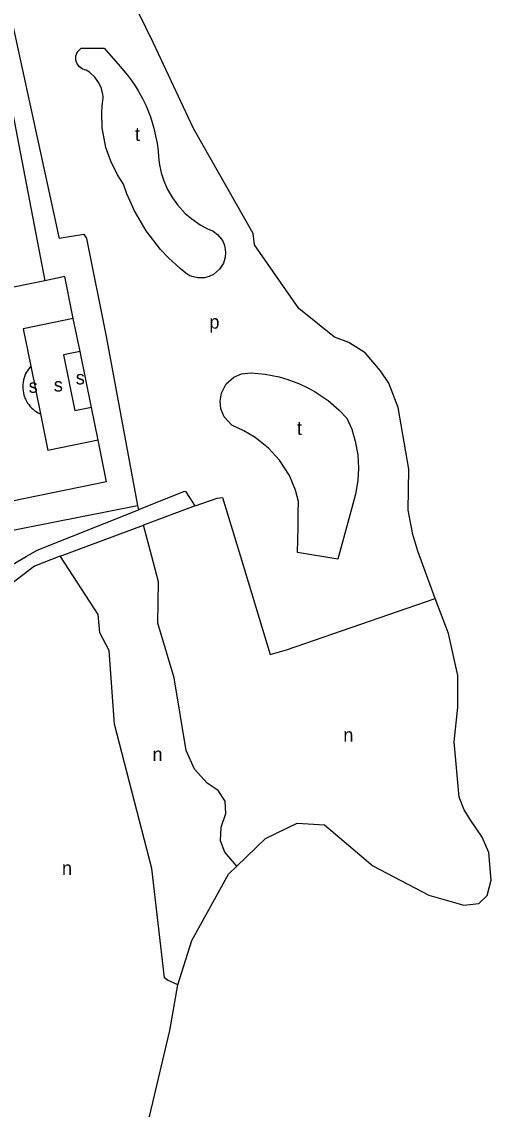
# Model space of a CAD drawing. Extents: x 160204 to 161526, y 379528 to 381793.
# Drawn here: x 161102.1 to 161240, y 380062.1 to 380381.3 of the extents above; entities that cross this region are included whole.
import ezdxf

# ---------------------------------------------------------------- set-up
doc = ezdxf.new("R2010")
doc.units = 0
doc.layers.add('BLT_Basislijn', color=7, linetype='Continuous')
doc.layers.add('BLT_Centroide', color=7, linetype='Continuous')

msp = doc.modelspace()

# ---------------------------------------------------------------- linework, layer by layer
at = {"layer": 'BLT_Basislijn'}
for p, q in [((161094.28, 380381.12), (161108.89, 380305.3)), ((161114.74, 380306.49), (161108.89, 380305.3)), ((161117.24, 380294.18), (161114.74, 380306.49)), ((161108.89, 380305.3), (161068.19, 380297.01)), ((161117.24, 380294.18), (161102.51, 380291.18)), ((161119.22, 380284.48), (161117.24, 380294.18)), ((161102.51, 380291.18), (161104.75, 380280.17)), ((161119.22, 380284.48), (161114.4, 380283.5)), ((161122.55, 380268.09), (161119.22, 380284.48)), ((161114.4, 380283.5), (161117.74, 380267.11)), ((161104.75, 380280.17), (161107.6, 380266.18)), ((161122.55, 380268.09), (161117.74, 380267.11)), ((161124.51, 380258.49), (161122.55, 380268.09)), ((161107.6, 380266.18), (161109.77, 380255.49)), ((161124.51, 380258.49), (161109.77, 380255.49)), ((161127, 380246.24), (161124.51, 380258.49)), ((161127, 380246.24), (161080.45, 380236.77)), ((161060.45, 380224.32), (161136.14, 380239.36)), ((161136.14, 380239.36), (161136.39, 380238.04)), ((161153, 380239.21), (161137.86, 380233.55)), ((161113.4, 380224.46), (161137.86, 380233.55)), ((161140.31, 380224.32), (161137.86, 380233.55)), ((161113.4, 380224.46), (161113.04, 380224.32)), ((161113.49, 380224.32), (161113.4, 380224.46))]:
    msp.add_line(p, q, dxfattribs=at)
for points in [[(161223.6, 380212.04), (161218.44, 380225.87), (161217.01, 380230.85), (161215.62, 380237.93), (161215.82, 380250), (161212.73, 380268.13), (161209.99, 380275.21), (161207.52, 380278.84), (161203.02, 380284.14), (161198.21, 380287.17), (161193.94, 380288.75), (161183.48, 380297.18), (161170.44, 380315.87), (161170.06, 380319.18), (161152.55, 380349.98), (161140.78, 380375.05), (161133.91, 380389.16), (161131.11, 380397.28)], [(161094.28, 380381.12), (161098, 380381.77), (161099.02, 380381.54), (161099.3, 380381.07), (161112.98, 380318.06), (161113.11, 380317.77), (161120.31, 380318.94), (161121.12, 380317.68), (161126.85, 380288.91), (161136.14, 380239.36)], [(161104.75, 380280.17), (161104.7, 380280.13), (161104.43, 380279.82), (161104.07, 380279.35), (161103.74, 380278.89), (161103.47, 380278.42), (161103.22, 380277.93), (161103, 380277.44), (161102.78, 380276.82), (161102.61, 380276.2), (161102.47, 380275.47), (161102.4, 380274.73), (161102.38, 380274.18), (161102.4, 380273.54), (161102.47, 380272.97), (161102.58, 380272.35), (161102.73, 380271.73), (161102.9, 380271.25), (161103.04, 380270.87), (161103.19, 380270.51), (161103.4, 380270.09), (161103.59, 380269.76), (161103.82, 380269.38), (161104.15, 380268.92), (161104.56, 380268.4), (161104.99, 380267.96), (161105.4, 380267.6), (161105.72, 380267.31), (161106.08, 380267.05), (161106.44, 380266.82), (161106.92, 380266.53), (161107.28, 380266.34), (161107.6, 380266.18)], [(161153, 380239.21), (161150.4, 380243.32), (161149.77, 380243.43), (161136.39, 380238.04)], [(161153, 380239.21), (161159.56, 380241.51), (161161.07, 380241.67), (161166.35, 380224.32)], [(161103.4, 380224.32), (161106.6, 380226.18), (161136.39, 380238.04)], [(161072.34, 380166.45), (161071.08, 380173.66), (161067.06, 380195.3), (161067.03, 380195.98), (161067.73, 380196.79), (161083.66, 380212.87), (161103.4, 380224.32)], [(161113.04, 380224.32), (161105.82, 380221.49), (161072.03, 380195.82), (161081.69, 380142.89), (161089.85, 380100), (161094.29, 380075.45), (161096.83, 380063.3), (161098.08, 380050.73), (161097.61, 380024.93), (161098.88, 379999.01), (161101.9, 379974.84)], [(161148, 380098.65), (161144.93, 380100), (161144.03, 380100.72), (161140.35, 380132.75), (161129.38, 380175.18), (161127.78, 380196.75), (161125.01, 380201.94), (161124.53, 380207.36), (161113.49, 380224.32)], [(161165.29, 380133.47), (161161.74, 380137.53), (161160.51, 380140.85), (161160.64, 380144.88), (161162.09, 380148.93), (161161.9, 380152.58), (161159.81, 380155.64), (161156.61, 380157.77), (161152.89, 380161.88), (161150.4, 380167.44), (161146.83, 380188.72), (161142.12, 380204.81), (161142.29, 380216.88), (161140.31, 380224.32)], [(161166.35, 380224.32), (161175.09, 380195.55), (161179.89, 380196.95), (161223.6, 380212.04)], [(161165.29, 380133.47), (161173.76, 380141.6), (161183.01, 380146.05), (161191.06, 380145.62), (161205.25, 380133.59), (161221.66, 380124.93), (161231.97, 380122.03), (161236.36, 380122.47), (161238.84, 380124.86), (161240.05, 380129.3), (161239.31, 380137.45), (161237.34, 380141.97), (161234.03, 380146.89), (161232.08, 380150), (161230.62, 380153.72), (161229.1, 380169.92), (161230.25, 380180.15), (161230.21, 380189.45), (161227.44, 380201.75), (161223.6, 380212.04)], [(161148, 380098.65), (161152.05, 380111.63), (161162.86, 380131.15), (161165.29, 380133.47)], [(161118.03, 379977.03), (161118.12, 379982.05), (161119.95, 379993.38), (161121.14, 380004.68), (161122.65, 380011.37), (161126.35, 380022.08), (161130.87, 380035.99), (161133.25, 380040), (161135.15, 380045.66), (161139.69, 380060.35), (161145.61, 380085.22), (161148, 380098.65)]]:
    msp.add_lwpolyline(points, dxfattribs=at)
for points in [[(161119.53, 380373.51), (161126.34, 380373.51), (161131, 380368.18), (161133.14, 380365.61), (161134.36, 380364.02), (161135.41, 380362.49), (161136.31, 380361.06), (161137.53, 380358.79), (161138.51, 380356.8), (161139.88, 380353.38), (161140.89, 380350.08), (161141.42, 380347.86), (161141.89, 380345.53), (161142.13, 380343.43), (161142.29, 380341.52), (161142.53, 380339.34), (161143.06, 380336.93), (161143.8, 380334.66), (161144.92, 380332.08), (161146.37, 380329.64), (161147.88, 380327.55), (161150.14, 380325.07), (161152.07, 380323.42), (161154.53, 380321.73), (161156.86, 380320.43), (161157.63, 380320.17), (161158.21, 380319.9), (161158.84, 380319.48), (161159.58, 380318.87), (161160.77, 380317.5), (161161.25, 380316.68), (161161.65, 380315.64), (161161.91, 380314.47), (161161.99, 380313.55), (161161.91, 380312.23), (161161.38, 380310.45), (161160.22, 380308.65), (161158.45, 380307.16), (161157.18, 380306.53), (161155.8, 380306.17), (161155.17, 380306.1), (161153.79, 380306.1), (161152.57, 380306.39), (161151.49, 380306.77), (161150.3, 380307.48), (161148.6, 380308.88), (161145.17, 380312.01), (161142.88, 380314.48), (161138.64, 380319.91), (161135.18, 380325.81), (161132.98, 380330.84), (161132.01, 380333.62), (161130.23, 380336.34), (161128.24, 380340.34), (161126.76, 380344.39), (161125.73, 380350.14), (161125.6, 380354.56), (161125.73, 380356.5), (161125.8, 380357.41), (161125.91, 380358.21), (161126.01, 380358.76), (161126.01, 380359.32), (161125.93, 380359.98), (161125.48, 380361.75), (161124.77, 380363.37), (161123.58, 380365.06), (161121.99, 380366.5), (161121.04, 380367.08), (161120.55, 380367.18), (161119.84, 380367.47), (161119.05, 380368.06), (161118.39, 380368.93), (161118.02, 380370.04), (161118.02, 380371.17), (161118.29, 380372.04), (161118.61, 380372.6), (161119.02, 380373.1)], [(161183.13, 380225.57), (161183.28, 380232.94), (161183.33, 380237.05), (161183.41, 380240.5), (161182.49, 380243.79), (161180.73, 380248.09), (161177.83, 380252.59), (161174.64, 380256.13), (161170.7, 380259.23), (161167.31, 380261.2), (161163.79, 380262.87), (161161.61, 380265.33), (161160.62, 380267.65), (161160.35, 380269.98), (161160.75, 380272.3), (161162.15, 380275.02), (161164.36, 380276.99), (161166.67, 380277.98), (161169.47, 380278.22), (161173.59, 380277.85), (161177.69, 380277.04), (161180.25, 380276.35), (161183.69, 380275.05), (161186.19, 380273.87), (161188.31, 380272.71), (161192.16, 380270.12), (161195.38, 380267.32), (161197.64, 380265), (161197.64, 380265), (161199.09, 380261.68), (161200.1, 380258.2), (161200.86, 380254.16), (161201.06, 380250.25), (161200.84, 380246.69), (161200.15, 380242.61), (161199.07, 380238.68), (161194.96, 380223.6)]]:
    msp.add_lwpolyline(points, close=True, dxfattribs=at)

# ---------------------------------------------------------------- texts
at = {"layer": 'BLT_Centroide'}
for s, p in [('t', (161135.37, 380346.34)), ('p', (161157.21, 380291.22)), ('s', (161117.96, 380274.85)), ('s', (161104.11, 380272.39)), ('s', (161111.51, 380272.76)), ('t', (161182.94, 380260.04)), ('n', (161196.56, 380169.97)), ('n', (161140.51, 380164.31)), ('n', (161113.9, 380130.89))]:
    msp.add_text(s, height=4, dxfattribs=at).set_placement(p)

doc.saveas('drawing.dxf')
